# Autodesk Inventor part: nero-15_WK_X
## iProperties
Shininess: 20.0
Length Units: 11269
Angle Units: 11279
Time Units: 11290
Mass Units: 11283
Length Display Precision: 2
Angle Display Precision: 2
Part Number: nero-15_WK_X
Material: Nichtrostender Stahl - 440C
Document SubType Name: Modellieren
Description: Ipc-25 /CXX/M18
Checked By: Alves
Created: 2005-08
Designer: Ohle
Manufacturer: Standard
Standards Organization: Custom
Density: 0.0
Volumn: 0.0
Area: 0.0
PropertySet Name: Model Information
Control State: 0
Master: False
Checked Out: False
BESTELLNUMMER: Ipc-25 /CXX/M18
ME: ST
Title: Ipc Sensoren
Author: Ohle
Comments: keine Bemerkung
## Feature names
1. Grundkörper pico+ [Revolution]
2. Pole [Extrusion]
3. Rundung Pole [Fillet]
4. Verdrehsicherung [Extrusion]
5. Bohrung Ausrichtung [Extrusion]
6. USW-Fläche Winkelkopf [Extrusion]
7. Extrusion6
8. Extrusion7
9. Extrusion8
